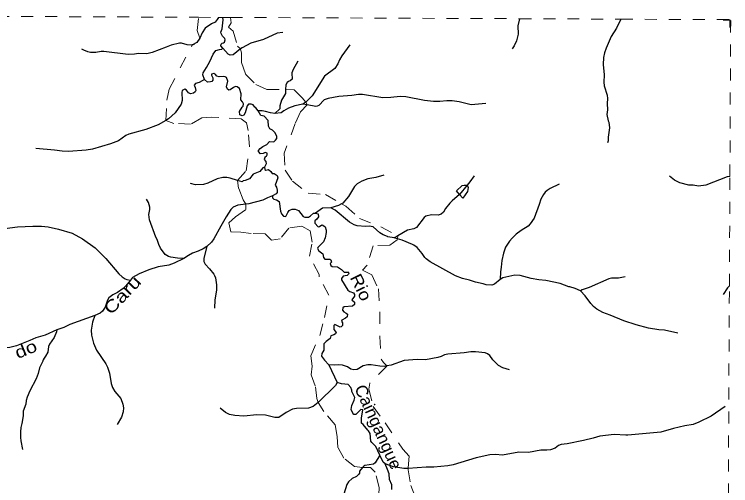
# Model space of a CAD drawing. Extents: x 551.6 to 577.6, y 7567 to 7594.7.
# Drawn here: x 571.58 to 577.56, y 7590.74 to 7594.67 of the extents above; entities that cross this region are included whole.
import ezdxf
from ezdxf.enums import TextEntityAlignment as Align

# ---------------------------------------------------------------- set-up
doc = ezdxf.new("R2010")
doc.units = 0
doc.header["$LTSCALE"] = 0.04
doc.linetypes.add('SHORT_DASHED', pattern=[2.7, 1.5, -1.2])
for name, color, linetype, lineweight in [('2', 7, 'Continuous', 25), ('21', 7, 'SHORT_DASHED', 13), ('53', 7, 'SHORT_DASHED', 13), ('55', 7, 'Continuous', 25), ('63', 7, 'Continuous', 25), ('7', 7, 'Continuous', 25)]:
    doc.layers.add(name, color=color, linetype=linetype, lineweight=lineweight)
doc.layers.add('61', color=7, linetype='Continuous')

msp = doc.modelspace()

# ---------------------------------------------------------------- linework, layer by layer
at = {"layer": '2'}
for points in [[(575.2939, 7593.1682), (575.2675, 7593.1986), (575.3154, 7593.244)], [(575.3575, 7593.2463), (575.3648, 7593.2263), (575.3596, 7593.1939), (575.321, 7593.1371), (575.2939, 7593.1682)], [(575.3154, 7593.244), (575.3323, 7593.247), (575.3575, 7593.2463)]]:
    msp.add_lwpolyline(points, dxfattribs=at)
at = {"layer": '21'}
for points in [[(573.1267, 7594.472), (573.1061, 7594.5358), (573.1172, 7594.6449)], [(573.3848, 7594.6437), (573.388, 7594.5998), (573.3676, 7594.5623), (573.4063, 7594.5302), (573.4406, 7594.4039), (573.4679, 7594.3816)], [(572.8446, 7593.785), (572.8521, 7593.9547), (572.8715, 7594.0455), (573.0655, 7594.4163)], [(573.4679, 7594.3816), (573.475, 7594.3461), (573.4761, 7594.2691), (573.5088, 7594.1696), (573.5947, 7594.0848), (573.6882, 7594.043), (573.8425, 7594.0435)], [(573.8425, 7594.0435), (573.9142, 7594.0393), (573.9813, 7593.9744), (574.0106, 7593.9364)], [(574.0222, 7593.9163), (573.9684, 7593.8564), (573.9233, 7593.7598), (573.8309, 7593.5131), (573.8395, 7593.3714), (573.8997, 7593.2792), (574.0306, 7593.1783), (574.175, 7593.1692), (574.3084, 7593.091)], [(574.0106, 7593.9364), (574.0243, 7593.9186), (574.0222, 7593.9163)], [(573.4428, 7593.2861), (573.5148, 7593.3665), (573.5421, 7593.567), (573.5313, 7593.7013), (573.516, 7593.7642), (573.4714, 7593.7984), (573.2868, 7593.8103), (573.2228, 7593.8118), (573.1447, 7593.8066), (573.0509, 7593.7545), (572.9109, 7593.7605), (572.8446, 7593.785)], [(573.5104, 7593.0871), (573.49, 7593.1238), (573.4513, 7593.2221), (573.4428, 7593.2861)], [(574.1146, 7591.4357), (574.1036, 7591.4669), (574.0902, 7591.5741), (574.0575, 7591.6663), (574.0649, 7591.7363), (574.0523, 7591.8234), (574.1297, 7591.993), (574.1684, 7592.1433), (574.2049, 7592.3301), (574.123, 7592.4819), (574.123, 7592.5012), (574.0419, 7592.6552), (574.0657, 7592.7698), (574.0479, 7592.8651), (573.9781, 7592.9038), (573.8709, 7592.8889), (573.7966, 7592.7981), (573.7251, 7592.7877), (573.6715, 7592.8397), (573.5554, 7592.8427), (573.469, 7592.8531), (573.3872, 7592.8575), (573.3693, 7592.9334), (573.4259, 7592.9825), (573.5124, 7593.042), (573.5104, 7593.0871)], [(574.3084, 7593.091), (574.3441, 7593.0701), (574.459, 7592.9692), (574.6378, 7592.9), (574.7795, 7592.8237), (574.7763, 7592.7997)], [(574.7763, 7592.7997), (574.7747, 7592.7901), (574.7124, 7592.7472), (574.5721, 7592.7401), (574.5235, 7592.5805), (574.484, 7592.5373), (574.5625, 7592.4975), (574.6176, 7592.3814), (574.6299, 7592.1891), (574.6295, 7591.9848), (574.6395, 7591.7962), (574.6604, 7591.7681), (574.6882, 7591.7391), (574.6887, 7591.7386)], [(574.6887, 7591.7386), (574.5455, 7591.5973), (574.5384, 7591.5448), (574.5727, 7591.402), (574.6736, 7591.2647), (574.8198, 7591.0448), (574.8749, 7590.989), (574.8652, 7590.8839)], [(574.4851, 7590.8927), (574.4191, 7590.9029), (574.3298, 7590.9699), (574.2785, 7591.0599), (574.274, 7591.1522), (574.2576, 7591.2474), (574.1609, 7591.3605), (574.1146, 7591.4357)], [(574.7788, 7590.1378), (574.7064, 7590.2422), (574.6729, 7590.3709), (574.6461, 7590.5153), (574.6372, 7590.6224), (574.6201, 7590.6693), (574.6231, 7590.7258), (574.5903, 7590.8538), (574.5501, 7590.8925), (574.4851, 7590.8927)], [(574.8652, 7590.8839), (574.8641, 7590.8725), (574.8879, 7590.7438), (574.9214, 7590.6567), (575.0267, 7590.4621), (575.0688, 7590.3122), (575.0554, 7590.2519), (575.0833, 7590.2143), (575.1823, 7590.1987), (575.2106, 7590.1816), (575.3873, 7590.0333)]]:
    msp.add_lwpolyline(points, dxfattribs=at)
at = {"layer": '53'}
for points in [[(567.5959, 7594.6695), (570.5848, 7594.6561), (571.0376, 7594.6541), (573.1172, 7594.6449), (573.2827, 7594.6441)], [(573.2827, 7594.6441), (573.3208, 7594.644), (573.3848, 7594.6437), (575.793, 7594.633), (576.6396, 7594.6292), (577.5554, 7594.6251)], [(577.4204, 7566.9518), (577.4226, 7567.3928), (577.4384, 7570.6314), (577.4446, 7571.9213), (577.4462, 7572.242), (577.4659, 7576.2813), (577.4696, 7577.0412), (577.4755, 7578.252), (577.4832, 7579.8317), (577.4989, 7583.0336), (577.5065, 7584.6034), (577.518, 7586.9644), (577.5184, 7587.0352), (577.519, 7587.1599), (577.5202, 7587.417), (577.5286, 7589.1281), (577.5292, 7589.2596), (577.5446, 7592.4063), (577.549, 7593.3187), (577.5554, 7594.6251)]]:
    msp.add_lwpolyline(points, dxfattribs=at)
at = {"layer": '55'}
msp.add_line((575.3575, 7593.2463), (575.2943, 7593.1685), dxfattribs=at)
at = {"layer": '63'}
msp.add_lwpolyline([(577.5522, 7594.5606), (577.5522, 7594.6222), (577.4915, 7594.6222)], dxfattribs=at)
at = {"layer": '7'}
for p, q in [((575.2943, 7593.1685), (575.2939, 7593.1682)), ((574.204, 7591.7494), (574.2721, 7591.6004))]:
    msp.add_line(p, q, dxfattribs=at)
for points in [[(573.2827, 7594.6441), (573.273, 7594.6257), (573.2568, 7594.605), (573.2247, 7594.5892), (573.1731, 7594.5546), (573.1458, 7594.5148), (573.1267, 7594.472)], [(573.3195, 7594.3885), (573.3033, 7594.4069), (573.3055, 7594.4209), (573.3136, 7594.4295), (573.3258, 7594.4321), (573.3346, 7594.4387), (573.339, 7594.4564), (573.3354, 7594.4689), (573.3169, 7594.4873), (573.3044, 7594.5087), (573.3036, 7594.5198), (573.314, 7594.55), (573.3236, 7594.6251), (573.3208, 7594.644)], [(575.793, 7594.633), (575.7799, 7594.5731), (575.7816, 7594.5055), (575.7687, 7594.4491), (575.7502, 7594.4057), (575.7317, 7594.3807)], [(576.6396, 7594.6292), (576.6024, 7594.5554), (576.559, 7594.4862), (576.5171, 7594.388), (576.5043, 7594.3493), (576.4954, 7594.3091), (576.4922, 7594.2528), (576.5002, 7594.1642), (576.4986, 7594.1047), (576.501, 7594.0741), (576.5252, 7593.9952), (576.5276, 7593.9671), (576.5252, 7593.9276), (576.5268, 7593.8729), (576.5236, 7593.8343), (576.5332, 7593.7812), (576.5381, 7593.7699), (576.5437, 7593.7248), (576.5349, 7593.646)], [(573.8203, 7594.5184), (573.7728, 7594.5135), (573.6585, 7594.4588), (573.5523, 7594.4282), (573.4798, 7594.3912), (573.4679, 7594.3816)], [(573.0655, 7594.4163), (573.0791, 7594.4201), (573.0565, 7594.4137), (573.0227, 7594.4153), (572.9736, 7594.4298), (572.9567, 7594.4298), (572.8891, 7594.4137), (572.8473, 7594.3952), (572.7298, 7594.3517), (572.6847, 7594.3405), (572.6171, 7594.3437), (572.5833, 7594.3381), (572.5302, 7594.3348), (572.3274, 7594.359), (572.3048, 7594.359), (572.2598, 7594.3509), (572.2147, 7594.3525), (572.1922, 7594.3574), (572.16, 7594.3703), (572.1431, 7594.3791)], [(573.1267, 7594.472), (573.1023, 7594.4345), (573.0655, 7594.4163)], [(573.1654, 7594.1263), (573.1536, 7594.1646), (573.1544, 7594.1823), (573.1846, 7594.2265), (573.2119, 7594.2773), (573.2384, 7594.3384), (573.2605, 7594.3671), (573.2915, 7594.3767), (573.3114, 7594.3781), (573.3195, 7594.3885)], [(573.4679, 7594.3816), (573.4062, 7594.3318), (573.3811, 7594.3288), (573.3627, 7594.3377), (573.3195, 7594.3885)], [(574.3788, 7594.4161), (574.312, 7594.3236), (574.2927, 7594.2898), (574.2782, 7594.256), (574.2533, 7594.2181), (574.1687, 7594.153), (574.0633, 7593.9896), (574.0106, 7593.9364), (573.988, 7593.9196)], [(573.9458, 7594.2793), (573.9064, 7594.2093), (573.8943, 7594.1819), (573.8943, 7594.1626), (573.8991, 7594.1449), (573.8983, 7594.128), (573.8822, 7594.1143), (573.8669, 7594.1095), (573.8549, 7594.1006), (573.8436, 7594.0822), (573.8425, 7594.0435)], [(573.1654, 7594.1263), (573.1218, 7594.1016), (573.0915, 7594.0935), (573.0812, 7594.0802), (573.0893, 7594.0604), (573.093, 7594.0346), (573.0886, 7594.0228), (573.0742, 7594.0121), (573.0491, 7594.007), (573.0344, 7594.0165), (573.0156, 7594.0368), (573.0013, 7594.0446), (572.9799, 7594.0357), (572.977, 7594.0195), (572.9807, 7593.9524), (572.9718, 7593.9222), (572.9206, 7593.8498), (572.865, 7593.798), (572.8446, 7593.785)], [(573.6135, 7593.8642), (573.5961, 7593.8915), (573.5876, 7593.8954), (573.5716, 7593.9163), (573.5571, 7593.922), (573.5338, 7593.9203), (573.5216, 7593.9081), (573.5069, 7593.8485), (573.4936, 7593.83), (573.4796, 7593.8227), (573.4604, 7593.8315), (573.4582, 7593.8595), (573.4796, 7593.8949), (573.4899, 7593.9052), (573.4907, 7593.9251), (573.4848, 7593.9406), (573.4693, 7593.9575), (573.473, 7594.0061), (573.459, 7594.0503), (573.4398, 7594.0658), (573.4265, 7594.0695), (573.4081, 7594.0606), (573.3793, 7594.0393), (573.3686, 7594.0389), (573.3575, 7594.0463), (573.3494, 7594.0662), (573.3607, 7594.1119), (573.3495, 7594.1433), (573.3398, 7594.1489), (573.3269, 7594.1505), (573.2883, 7594.1481), (573.269, 7594.1545), (573.2641, 7594.1578), (573.2625, 7594.165), (573.2447, 7594.1761), (573.2256, 7594.1702), (573.2241, 7594.1614), (573.2355, 7594.1395), (573.2355, 7594.1211), (573.2266, 7594.1101), (573.2156, 7594.1064), (573.1927, 7594.1056), (573.1654, 7594.1263)], [(573.8425, 7594.0435), (573.8416, 7594.0092), (573.8077, 7593.9547), (573.7952, 7593.9076), (573.7944, 7593.881), (573.7546, 7593.8443)], [(574.4858, 7594.0025), (574.452, 7594.0017), (574.3957, 7593.9936), (574.2879, 7593.9856), (574.1993, 7593.9695), (574.1655, 7593.9558), (574.1213, 7593.9091), (574.1076, 7593.9035), (574.0963, 7593.9027), (574.0222, 7593.9163), (573.988, 7593.9196)], [(575.512, 7593.926), (575.3904, 7593.9163), (575.3679, 7593.9196), (575.2906, 7593.9413), (575.2311, 7593.9501), (575.1876, 7593.9501), (575.1297, 7593.9437), (575.0766, 7593.9437), (575.0009, 7593.951), (574.8448, 7593.9831), (574.7997, 7593.9848), (574.7209, 7593.9759), (574.6532, 7593.9743), (574.4858, 7594.0025)], [(573.988, 7593.9196), (573.9201, 7593.9067), (573.8678, 7593.8874), (573.8283, 7593.8658), (573.8074, 7593.8495), (573.7546, 7593.8443)], [(573.6829, 7593.4876), (573.688, 7593.498), (573.688, 7593.5113), (573.6718, 7593.5194), (573.657, 7593.5098), (573.6349, 7593.5061), (573.6182, 7593.5268), (573.6182, 7593.5349), (573.6311, 7593.5522), (573.6536, 7593.5695), (573.6864, 7593.5853), (573.71, 7593.6097), (573.7461, 7593.6082), (573.7601, 7593.62), (573.7697, 7593.6362), (573.7697, 7593.6509), (573.7565, 7593.6826), (573.7336, 7593.7047), (573.7115, 7593.7143), (573.6997, 7593.7378), (573.6967, 7593.7843), (573.6639, 7593.82), (573.6373, 7593.8267), (573.6135, 7593.8642)], [(573.7546, 7593.8443), (573.717, 7593.848), (573.6765, 7593.8598), (573.647, 7593.8642), (573.6135, 7593.8642)], [(572.8446, 7593.785), (572.7797, 7593.7497), (572.6767, 7593.7103), (572.535, 7593.6701), (572.5109, 7593.6588), (572.4481, 7593.6161), (572.3837, 7593.5896), (572.2324, 7593.5461), (572.1809, 7593.5381), (572.0312, 7593.5268), (571.9797, 7593.5284), (571.9153, 7593.5373), (571.7584, 7593.551)], [(576.5349, 7593.646), (576.5332, 7593.6145), (576.5286, 7593.5991)], [(573.6829, 7593.4876), (573.6703, 7593.4773), (573.6652, 7593.4604), (573.6777, 7593.4434), (573.6803, 7593.4239), (573.6671, 7593.3952)], [(573.6671, 7593.3952), (573.6525, 7593.3893), (573.6271, 7593.3602), (573.5716, 7593.3369), (573.541, 7593.2991), (573.5056, 7593.2846), (573.4887, 7593.2814), (573.4798, 7593.2749), (573.4428, 7593.2861)], [(573.6671, 7593.3952), (573.6685, 7593.376), (573.6774, 7593.3716), (573.7017, 7593.3767), (573.7209, 7593.3591), (573.7319, 7593.3443), (573.7489, 7593.3421), (573.7725, 7593.3252), (573.7784, 7593.3067), (573.7559, 7593.2467), (573.767, 7593.229), (573.7736, 7593.2032), (573.7736, 7593.1856), (573.7633, 7593.1738), (573.733, 7593.1568)], [(573.4428, 7593.2861), (573.3817, 7593.3047), (573.3527, 7593.3095), (573.3205, 7593.3103), (573.2722, 7593.2999), (573.1933, 7593.2628), (573.1595, 7593.2516), (573.0919, 7593.2476), (573.0509, 7593.2596)], [(574.6637, 7593.3289), (574.5969, 7593.3095), (574.5293, 7593.2991), (574.4786, 7593.2789), (574.4408, 7593.2564), (574.419, 7593.2347), (574.3675, 7593.151), (574.3192, 7593.0971), (574.3084, 7593.091)], [(575.4162, 7593.3248), (575.38, 7593.2725), (575.3575, 7593.2463)], [(577.549, 7593.3187), (577.5264, 7593.3144), (577.3477, 7593.2468), (577.2882, 7593.2371), (577.2431, 7593.2451), (577.2077, 7593.2467), (577.132, 7593.2653), (577.087, 7593.2886), (577.0443, 7593.3216)], [(576.1252, 7593.2556), (576.0488, 7593.2178), (576.0238, 7593.2017), (576.0069, 7593.1864), (575.9932, 7593.1679), (575.9731, 7593.1293), (575.9594, 7593.0842), (575.9152, 7592.9715), (575.8838, 7592.9224), (575.8669, 7592.9047), (575.8073, 7592.8669), (575.7671, 7592.8363), (575.7317, 7592.8049), (575.7107, 7592.78), (575.6769, 7592.7285), (575.66, 7592.6802), (575.6464, 7592.619), (575.6415, 7592.5627)], [(575.2939, 7593.1682), (575.2327, 7593.1156), (575.2134, 7593.0954), (575.1763, 7593.0504), (575.1602, 7593.0214), (575.1393, 7593.0037), (575.1152, 7592.9965), (575.0589, 7592.9989), (575.0138, 7592.9876), (574.9993, 7592.9771), (574.9357, 7592.8926), (574.9124, 7592.883), (574.8609, 7592.8701), (574.7795, 7592.8237), (574.7499, 7592.8069)], [(572.9948, 7592.6342), (572.9422, 7592.6367), (572.8859, 7592.6448), (572.8666, 7592.6512), (572.8392, 7592.6681), (572.7998, 7592.7204), (572.7845, 7592.751), (572.7708, 7592.7945), (572.7603, 7592.8138), (572.7088, 7592.957), (572.7032, 7593.0021), (572.7104, 7593.0424), (572.7104, 7593.0617), (572.6992, 7593.1003), (572.6815, 7593.1285)], [(573.733, 7593.1568), (573.6928, 7593.1414), (573.653, 7593.1215), (573.5362, 7593.0898), (573.5104, 7593.0871)], [(573.733, 7593.1568), (573.7345, 7593.1391), (573.7448, 7593.1288), (573.7677, 7593.1237), (573.7898, 7593.1104), (573.8009, 7593.0279), (573.8082, 7593.0077), (573.8259, 7592.9868), (573.842, 7592.9852), (573.8487, 7592.9902), (573.8612, 7593.0182), (573.8737, 7593.0337), (573.8826, 7593.0403), (573.8988, 7593.0455), (573.9224, 7593.0455), (573.9497, 7593.0352), (573.9885, 7592.9852), (574.0046, 7592.9787), (574.0352, 7592.9803), (574.0504, 7592.9892), (574.0764, 7593.0117), (574.0926, 7593.0139)], [(573.5104, 7593.0871), (573.446, 7593.0802), (573.4058, 7593.0633), (573.3873, 7593.0424), (573.3486, 7592.9828), (573.302, 7592.9055), (573.244, 7592.7993), (573.2255, 7592.7719), (573.1863, 7592.7343)], [(574.2204, 7593.0564), (574.1511, 7593.0535), (574.0926, 7593.0139)], [(574.3084, 7593.091), (574.2846, 7593.0777), (574.2204, 7593.0564)], [(574.7499, 7592.8069), (574.6946, 7592.8158), (574.6942, 7592.8186), (574.6581, 7592.8323), (574.629, 7592.8474), (574.5744, 7592.899), (574.5398, 7592.9056), (574.5081, 7592.9012), (574.4399, 7592.9067), (574.4156, 7592.9141), (574.3756, 7592.9369), (574.2551, 7593.0375), (574.2204, 7593.0564)], [(574.0926, 7593.0139), (574.1147, 7593.0058), (574.1162, 7592.983), (574.1037, 7592.9638), (574.086, 7592.9498), (574.0871, 7592.9303), (574.1136, 7592.9001), (574.1269, 7592.9009), (574.1461, 7592.9149), (574.1542, 7592.9127), (574.1726, 7592.8987), (574.1822, 7592.8721), (574.1822, 7592.8515), (574.1719, 7592.8057), (574.1599, 7592.7738), (574.1108, 7592.7277), (574.1092, 7592.7183), (574.1203, 7592.6976), (574.1527, 7592.6733), (574.1579, 7592.6439), (574.1704, 7592.6306), (574.2114, 7592.6295), (574.2203, 7592.623), (574.2246, 7592.6054), (574.2157, 7592.5929), (574.2201, 7592.5767), (574.2323, 7592.5675), (574.2763, 7592.5656), (574.3095, 7592.5442), (574.3321, 7592.5216), (574.3699, 7592.5216), (574.3675, 7592.5176), (574.3699, 7592.5087), (574.3667, 7592.5039)], [(571.4558, 7592.8798), (571.6079, 7592.8991), (571.7334, 7592.9055), (571.8075, 7592.9039), (571.8638, 7592.8975), (571.9475, 7592.8798), (572.0618, 7592.8452), (572.1495, 7592.7993), (572.2549, 7592.7244), (572.3443, 7592.6343), (572.4513, 7592.5071), (572.4803, 7592.4822), (572.506, 7592.4653), (572.5189, 7592.4597), (572.5503, 7592.4556)], [(574.9011, 7592.7518), (574.8158, 7592.7888), (574.7763, 7592.7997), (574.7499, 7592.8069)], [(575.6326, 7592.4612), (575.5868, 7592.4218), (575.5643, 7592.4114), (575.516, 7592.4154), (575.4902, 7592.4242), (575.4259, 7592.4387), (575.376, 7592.4548), (575.3196, 7592.4685), (575.2601, 7592.491), (575.0492, 7592.6061), (575.0146, 7592.6311), (575.0033, 7592.6432), (574.9816, 7592.677), (574.9397, 7592.7269), (574.914, 7592.747), (574.9011, 7592.7518)], [(573.1863, 7592.7343), (573.1563, 7592.7164), (573.1129, 7592.6963), (573.0678, 7592.6802), (573.0332, 7592.6609), (572.9948, 7592.6342)], [(573.1863, 7592.7343), (573.1611, 7592.6375), (573.1611, 7592.611), (573.1716, 7592.5884), (573.2094, 7592.5482), (573.2448, 7592.5031), (573.2513, 7592.4935), (573.2577, 7592.4742), (573.2658, 7592.4162), (573.2658, 7592.3711), (573.2521, 7592.2907), (573.2513, 7592.2223)], [(572.9948, 7592.6342), (572.9133, 7592.5949), (572.8682, 7592.5804), (572.7789, 7592.5659), (572.7024, 7592.5417), (572.6203, 7592.5079)], [(575.6415, 7592.5627), (575.6351, 7592.5241), (575.6326, 7592.4612)], [(572.5503, 7592.4556), (572.5101, 7592.4065), (572.4883, 7592.3848), (572.44, 7592.351), (572.4014, 7592.3333), (572.37, 7592.3084), (572.3579, 7592.2874), (572.3386, 7592.2295), (572.3153, 7592.1949), (572.2968, 7592.1788), (572.2522, 7592.1595)], [(572.6203, 7592.5079), (572.5666, 7592.4756), (572.5503, 7592.4556)], [(574.3667, 7592.5039), (574.3555, 7592.4934), (574.3241, 7592.487), (574.3088, 7592.4677), (574.3102, 7592.4566), (574.3611, 7592.3703), (574.3796, 7592.359), (574.4085, 7592.3478), (574.4182, 7592.3357), (574.4182, 7592.3213), (574.3952, 7592.2901), (574.4174, 7592.2716), (574.4166, 7592.2518), (574.3997, 7592.237), (574.3326, 7592.2319), (574.32, 7592.223), (574.3186, 7592.2046), (574.3289, 7592.1899), (574.3488, 7592.1803), (574.3606, 7592.17), (574.3554, 7592.1494), (574.3436, 7592.139), (574.3133, 7592.1219), (574.3089, 7592.1123), (574.3178, 7592.0991), (574.3178, 7592.0865), (574.3163, 7592.077), (574.306, 7592.0659), (574.2979, 7592.0622), (574.2536, 7592.0843), (574.2462, 7592.0755), (574.2444, 7592.042), (574.2643, 7592.0181), (574.2599, 7592.0063), (574.2459, 7591.9982), (574.2197, 7591.9905), (574.2149, 7591.968), (574.1802, 7591.943), (574.1633, 7591.9238), (574.1633, 7591.8723), (574.1456, 7591.8428), (574.1434, 7591.8207), (574.1686, 7591.7877), (574.204, 7591.7494)], [(576.0134, 7592.4524), (575.9554, 7592.4572), (575.8926, 7592.4677), (575.8009, 7592.4935), (575.7558, 7592.4967), (575.6544, 7592.4741), (575.6326, 7592.4612)], [(576.3038, 7592.3653), (576.258, 7592.3856), (576.2129, 7592.4001), (576.2049, 7592.4001), (576.1341, 7592.4259), (576.0134, 7592.4524)], [(576.6757, 7592.4814), (576.6186, 7592.4701), (576.5622, 7592.4701), (576.5397, 7592.4653), (576.3739, 7592.3937), (576.3176, 7592.3751), (576.3038, 7592.3653)], [(577.5446, 7592.4063), (577.5296, 7592.3894), (577.4918, 7592.3349)], [(577.1135, 7592.0138), (577.0033, 7592.0388), (576.955, 7592.0396), (576.8697, 7592.054), (576.7667, 7592.0814), (576.6652, 7592.116), (576.551, 7592.1635), (576.4882, 7592.186), (576.4391, 7592.2126), (576.4125, 7592.2343), (576.3892, 7592.2601), (576.3414, 7592.3233), (576.3038, 7592.3653)], [(572.2522, 7592.1595), (572.0425, 7592.0846), (571.9942, 7592.0589), (571.9355, 7592.0406)], [(572.2522, 7592.1595), (572.2324, 7592.104), (572.2219, 7592.0364), (572.2243, 7591.9961), (572.2404, 7591.9285), (572.2654, 7591.8714), (572.3435, 7591.7579), (572.3587, 7591.7289), (572.3748, 7591.6806), (572.3893, 7591.5937), (572.3998, 7591.5599), (572.4191, 7591.5277), (572.4682, 7591.4682), (572.4867, 7591.4199), (572.4899, 7591.3909), (572.4883, 7591.3571), (572.4738, 7591.312), (572.4392, 7591.2517)], [(571.9355, 7592.0406), (571.9322, 7592.0235), (571.9129, 7591.976), (571.8742, 7591.9213), (571.8646, 7591.9028), (571.859, 7591.8545), (571.8413, 7591.8207), (571.8236, 7591.7949), (571.8236, 7591.7901), (571.8187, 7591.7869), (571.8187, 7591.7804), (571.7906, 7591.7241), (571.7785, 7591.6758), (571.7624, 7591.6323), (571.7101, 7591.5317), (571.6875, 7591.4794), (571.6795, 7591.4505), (571.6763, 7591.4215), (571.6553, 7591.3635), (571.6529, 7591.3249)], [(571.9355, 7592.0406), (571.8381, 7591.9969), (571.7592, 7591.9736), (571.7109, 7591.9518)], [(571.7109, 7591.9518), (571.5998, 7591.906), (571.5419, 7591.8939), (571.4775, 7591.8899), (571.4582, 7591.885), (571.3702, 7591.849)], [(575.7116, 7591.708), (575.6544, 7591.7241), (575.619, 7591.7434), (575.5707, 7591.7917), (575.5458, 7591.8263), (575.5273, 7591.8416), (575.5079, 7591.8488), (575.4259, 7591.8561), (575.3872, 7591.8561), (575.3325, 7591.848), (575.1973, 7591.8384), (575.1683, 7591.8319), (575.141, 7591.819), (575.112, 7591.8102), (575.009, 7591.7917), (574.9414, 7591.7925), (574.8319, 7591.7836), (574.7225, 7591.745), (574.6882, 7591.7391)], [(574.6882, 7591.7391), (574.6661, 7591.7353), (574.6291, 7591.7369), (574.5567, 7591.7498), (574.5277, 7591.7482), (574.4891, 7591.7394), (574.4389, 7591.7104), (574.4124, 7591.7059), (574.3866, 7591.7133), (574.36, 7591.7317), (574.3168, 7591.7466), (574.2879, 7591.7482), (574.2492, 7591.745), (574.204, 7591.7494)], [(574.2721, 7591.6004), (574.258, 7591.5766), (574.1146, 7591.4357)], [(574.3965, 7591.5269), (574.3941, 7591.5277), (574.3941, 7591.5374), (574.3871, 7591.5606), (574.365, 7591.5842), (574.3089, 7591.5916), (574.2721, 7591.6004)], [(574.6299, 7590.9948), (574.5949, 7591.069), (574.5618, 7591.1021), (574.5544, 7591.1139), (574.5485, 7591.1773), (574.5357, 7591.1994), (574.5293, 7591.2034), (574.4892, 7591.2513), (574.4756, 7591.2627), (574.477, 7591.3047), (574.4859, 7591.3725), (574.4711, 7591.3762), (574.4287, 7591.3353), (574.4118, 7591.3361), (574.4037, 7591.345), (574.3901, 7591.3756), (574.396, 7591.4102), (574.4151, 7591.4551), (574.421, 7591.4765), (574.3965, 7591.5269)], [(574.1146, 7591.4357), (574.0738, 7591.4013), (574.0352, 7591.3869), (573.9338, 7591.3861), (573.9, 7591.3796), (573.8484, 7591.3514), (573.7857, 7591.3104), (573.7519, 7591.3088), (573.6746, 7591.3281), (573.6038, 7591.3329), (573.4959, 7591.3201), (573.4187, 7591.3265), (573.3752, 7591.3362), (573.3414, 7591.3506), (573.2972, 7591.3877)], [(577.5095, 7591.4014), (577.3928, 7591.3201), (577.2898, 7591.2702), (577.2415, 7591.2516), (577.1739, 7591.2404), (577.0773, 7591.2187), (576.9727, 7591.1881), (576.6974, 7591.1615), (576.6813, 7591.1623)], [(571.6529, 7591.3249), (571.6433, 7591.2589), (571.6352, 7591.2267), (571.632, 7591.1913), (571.632, 7591.143), (571.6352, 7591.1141), (571.6497, 7591.0424)], [(576.6813, 7591.1623), (576.5848, 7591.1671), (576.464, 7591.1543), (576.4077, 7591.1366), (576.3272, 7591.1173), (576.1904, 7591.0907), (576.1421, 7591.0851), (576.1204, 7591.0762), (576.0914, 7591.0553), (576.0536, 7591.0408), (576.0214, 7591.0368), (575.9731, 7591.0368), (575.8685, 7591.0175)], [(575.8685, 7591.0175), (575.788, 7591.0215), (575.6512, 7590.9973), (575.5949, 7591.0014), (575.5466, 7590.9998), (575.4323, 7590.974), (575.2408, 7590.9161), (575.1973, 7590.9064), (575.0798, 7590.8951), (575.0154, 7590.8951), (574.8652, 7590.8839)], [(574.6299, 7590.9948), (574.5891, 7590.9331), (574.5751, 7590.9213), (574.5052, 7590.9096), (574.4963, 7590.9048), (574.4851, 7590.8927)], [(574.6723, 7590.9224), (574.6568, 7590.9378), (574.6299, 7590.9948)], [(574.7283, 7590.7087), (574.7298, 7590.7485), (574.7099, 7590.7927), (574.7069, 7590.8391), (574.6936, 7590.8774), (574.6723, 7590.9224)], [(574.8652, 7590.8839), (574.8303, 7590.8839), (574.7418, 7590.9), (574.6723, 7590.9224)], [(574.4851, 7590.8927), (574.4601, 7590.8613), (574.4585, 7590.846), (574.4504, 7590.8356), (574.4335, 7590.8195), (574.3973, 7590.8018), (574.3683, 7590.7744), (574.3546, 7590.7519), (574.3281, 7590.6722)]]:
    msp.add_lwpolyline(points, dxfattribs=at)

# ---------------------------------------------------------------- texts
at = {"layer": '61'}
for s, rotation, width, p in [('Rio', 296.038, 1.15, (574.427, 7592.3732)), ('Caru', 46.624, 1.3, (572.5177, 7592.2964)), ('do', 22.466, 1.25, (571.6951, 7591.8322)), ('Caingangue', 294.407, 1.05, (574.5712, 7591.2104))]:
    msp.add_text(s, height=0.1, rotation=rotation, dxfattribs=dict(at, width=width)).set_placement(p, align=Align.CENTER)

doc.saveas('drawing.dxf')
